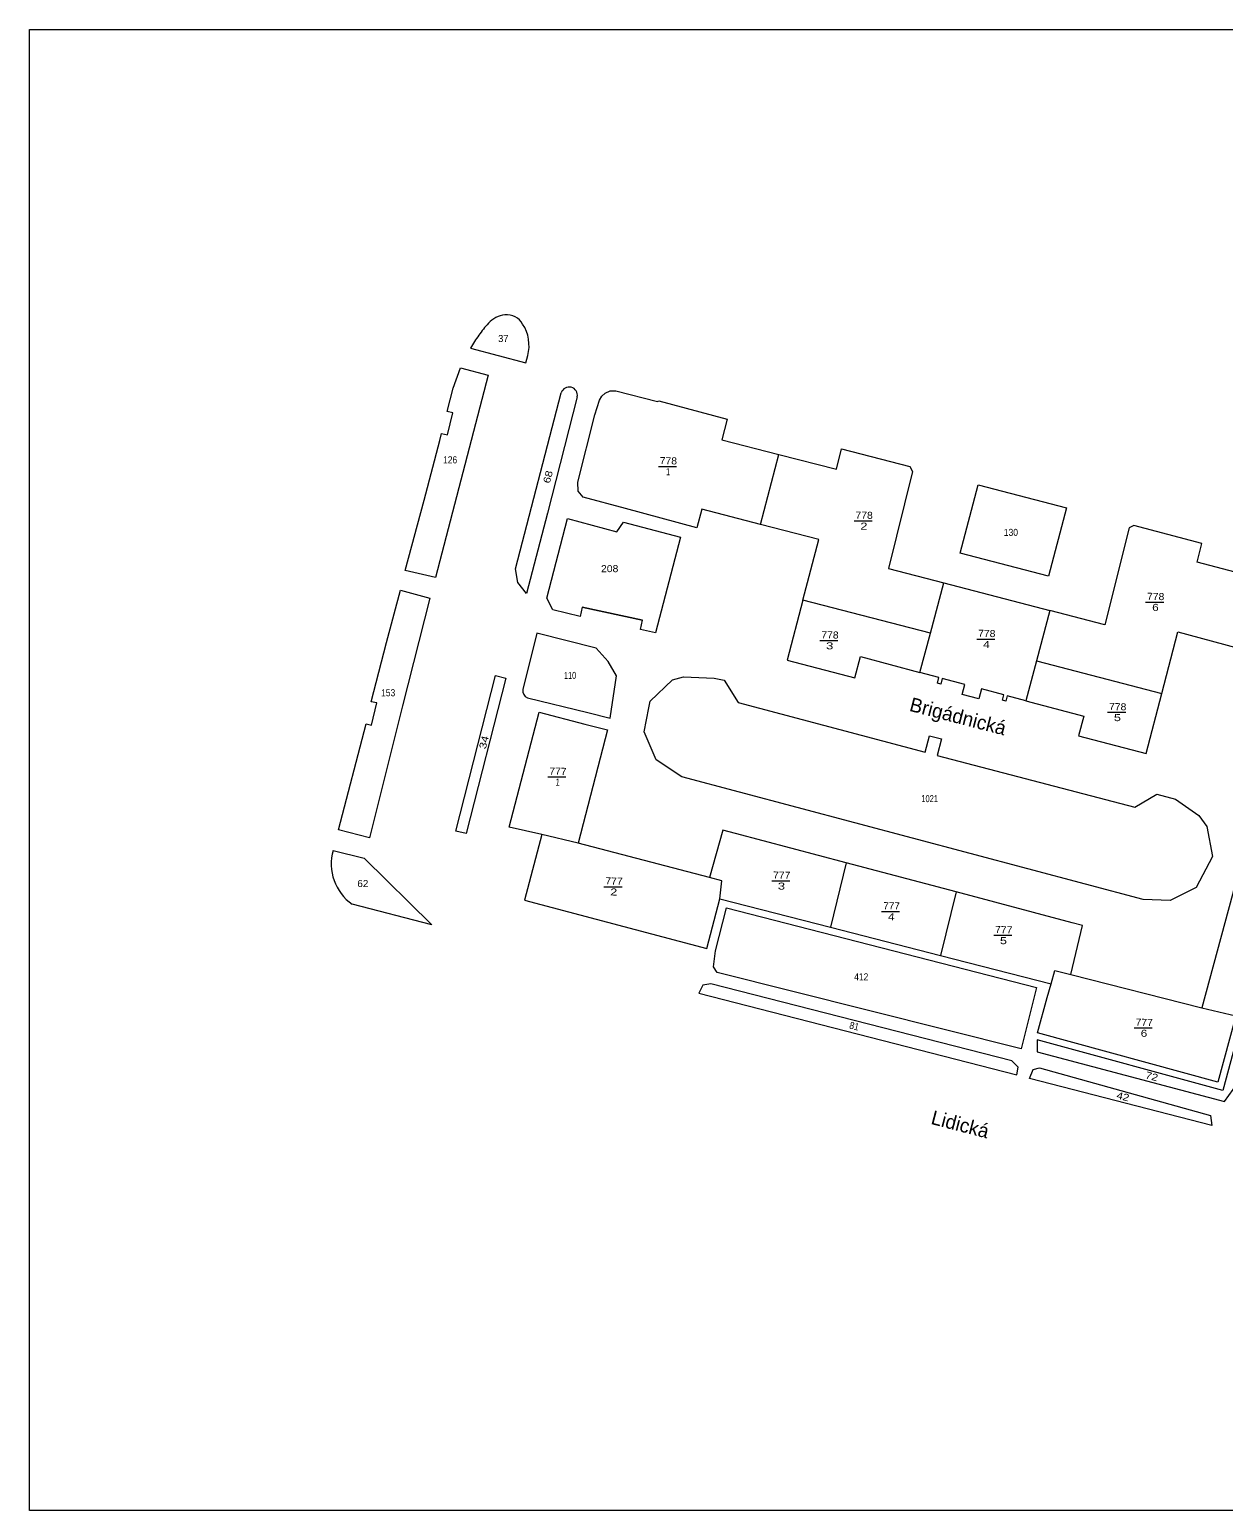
# Model space of a CAD drawing. Extents: x -843443 to -843145, y -1003566 to -1003356.
# Drawn here: x -843442.9 to -843273.6, y -1003566.1 to -1003356.1 of the extents above; entities that cross this region are included whole.
import ezdxf
from ezdxf.enums import TextEntityAlignment as Align

# ---------------------------------------------------------------- set-up
doc = ezdxf.new("R2010")
doc.units = 0
doc.header["$LTSCALE"] = 0.4
doc.layers.add('20', color=7, linetype='Continuous')
for name, color, linetype, lineweight in [('35', 7, 'Continuous', 13), ('38', 7, 'Continuous', 13), ('43', 7, 'Continuous', 13), ('44', 7, 'Continuous', 13)]:
    doc.layers.add(name, color=color, linetype=linetype, lineweight=lineweight)

msp = doc.modelspace()

# ---------------------------------------------------------------- linework, layer by layer
at = {"layer": '35'}
for p, q in [((-843353.765, -1003418.066), (-843351.205, -1003418.066)), ((-843326.004, -1003425.786), (-843323.444, -1003425.786)), ((-843284.663, -1003437.309), (-843282.103, -1003437.309)), ((-843330.851, -1003442.758), (-843328.291, -1003442.758)), ((-843308.615, -1003442.552), (-843306.055, -1003442.552)), ((-843290.05, -1003452.939), (-843287.49, -1003452.939)), ((-843369.424, -1003462.093), (-843366.864, -1003462.093)), ((-843361.475, -1003477.669), (-843358.915, -1003477.669)), ((-843337.695, -1003476.835), (-843335.135, -1003476.835)), ((-843322.113, -1003481.18), (-843319.553, -1003481.18)), ((-843306.214, -1003484.57), (-843303.654, -1003484.57)), ((-843286.286, -1003497.709), (-843283.726, -1003497.709))]:
    msp.add_line(p, q, dxfattribs=at)
at = {"layer": '38'}
for p, q in [((-843327.15, -1003474.27), (-843329.37, -1003483.4)), ((-843311.54, -1003478.41), (-843313.76, -1003487.41))]:
    msp.add_line(p, q, dxfattribs=at)
for points in [[(-843339.26, -1003426.3), (-843347.62, -1003424.13), (-843348.31, -1003426.79), (-843358.44, -1003424.06), (-843364.43, -1003422.42), (-843365.14, -1003421.56), (-843365.19, -1003420.28), (-843362.75, -1003410.74), (-843362.1, -1003408.66), (-843361.79, -1003408.11), (-843361.31, -1003407.67), (-843360.6, -1003407.36), (-843359.81, -1003407.34), (-843353.87, -1003408.86), (-843353.72, -1003408.78), (-843344.03, -1003411.39), (-843344.76, -1003414.3), (-843336.68, -1003416.38)], [(-843333.26, -1003437.02), (-843331.03, -1003428.44), (-843339.26, -1003426.3), (-843336.68, -1003416.38), (-843328.52, -1003418.48), (-843327.79, -1003415.57), (-843318.1, -1003418.09), (-843317.72, -1003418.79), (-843321.15, -1003432.55), (-843313.28, -1003434.6)], [(-843269.27, -1003433.78), (-843277.38, -1003431.66), (-843276.69, -1003428.99), (-843286.35, -1003426.45), (-843287.02, -1003426.78), (-843290.46, -1003440.54), (-843298.24, -1003438.52), (-843300.14, -1003445.64), (-843282.35, -1003450.26), (-843280.09, -1003441.55), (-843271.86, -1003443.76)], [(-843301.65, -1003451.31), (-843304.3, -1003450.6), (-843304.5, -1003451.35), (-843304.97, -1003451.23), (-843304.77, -1003450.48), (-843307.96, -1003449.62), (-843308.33, -1003451.03), (-843310.68, -1003450.41), (-843310.3, -1003449), (-843313.51, -1003448.14), (-843313.73, -1003448.95), (-843314.19, -1003448.83), (-843313.97, -1003448.02), (-843316.68, -1003447.29), (-843315.19, -1003441.72), (-843313.28, -1003434.6), (-843298.24, -1003438.52)], [(-843315.19, -1003441.72), (-843333.26, -1003437.02), (-843335.49, -1003445.57), (-843325.88, -1003448.07), (-843325.08, -1003445.05), (-843316.68, -1003447.29)], [(-843300.14, -1003445.64), (-843301.65, -1003451.31), (-843293.44, -1003453.51), (-843294.19, -1003456.3), (-843284.57, -1003458.8), (-843282.35, -1003450.26)], [(-843370.29, -1003470.29), (-843372.73, -1003479.58), (-843346.91, -1003486.42), (-843345.06, -1003479.38), (-843344.76, -1003476.84), (-843346.53, -1003476.38), (-843365.15, -1003471.48)], [(-843295.27, -1003490.11), (-843293.64, -1003483.16), (-843295.06, -1003482.78), (-843311.54, -1003478.41), (-843327.15, -1003474.27), (-843342.84, -1003470.11), (-843344.6, -1003469.64), (-843346.53, -1003476.38)], [(-843267.1, -1003497.15), (-843262.83, -1003481.4), (-843262.362, -1003479.672), (-843271.96, -1003477.07), (-843272.36, -1003478.76), (-843276.71, -1003494.83)], [(-843345.06, -1003479.38), (-843329.37, -1003483.4), (-843313.76, -1003487.41), (-843298.07, -1003491.44)]]:
    msp.add_lwpolyline(points, dxfattribs=at)
for points in [[(-843370.69, -1003452.93), (-843364.18, -1003454.6), (-843361, -1003455.42), (-843365.15, -1003471.48), (-843370.29, -1003470.29), (-843374.92, -1003469.22)], [(-843300, -1003498.41), (-843298.61, -1003493.41), (-843298.07, -1003491.44), (-843297.556, -1003489.565), (-843295.27, -1003490.11), (-843276.71, -1003494.83), (-843271.88, -1003496), (-843274.44, -1003505.383)]]:
    msp.add_lwpolyline(points, close=True, dxfattribs=at)
at = {"layer": '43'}
for p, q in [((-843364.569, -1003438.014), (-843356.009, -1003439.864)), ((-843354.174, -1003441.669), (-843356.3, -1003441.21)), ((-843385.893, -1003483.063), (-843397.172, -1003480.167))]:
    msp.add_line(p, q, dxfattribs=at)
for points in [[(-843380.42, -1003401.29), (-843372.572, -1003403.361), (-843372.284, -1003402.359)], [(-843372.483, -1003436.085), (-843373.686, -1003434.546), (-843374.004, -1003432.574), (-843367.537, -1003407.623)], [(-843365.264, -1003408.202), (-843369.47, -1003424.72), (-843372.483, -1003436.085)], [(-843372.339, -1003450.901), (-843363.76, -1003452.98), (-843360.58, -1003453.79), (-843359.72, -1003447.77), (-843360.88, -1003445.72), (-843362.57, -1003443.84), (-843371.01, -1003441.72), (-843372.969, -1003449.709)], [(-843399.886, -1003472.516), (-843395.497, -1003473.643), (-843385.893, -1003483.063)]]:
    msp.add_lwpolyline(points, dxfattribs=at)
for points in [[(-843383.704, -1003410.282), (-843382.85, -1003406.95), (-843381.84, -1003404.086), (-843377.88, -1003405.132), (-843385.354, -1003433.806), (-843389.68, -1003432.85), (-843386.96, -1003422.84), (-843384.76, -1003414.4), (-843384.504, -1003413.403), (-843383.644, -1003413.601), (-843382.924, -1003410.461)], [(-843308.42, -1003420.674), (-843295.91, -1003423.94), (-843298.44, -1003433.632), (-843310.95, -1003430.366)], [(-843354.174, -1003441.669), (-843356.3, -1003441.21), (-843356.009, -1003439.864), (-843364.569, -1003438.014), (-843364.86, -1003439.36), (-843368.74, -1003438.42), (-843369.58, -1003436.74), (-843366.66, -1003425.44), (-843359.65, -1003427.35), (-843358.72, -1003425.99), (-843350.632, -1003428.101)], [(-843399.14, -1003469.61), (-843395.21, -1003454.58), (-843394.43, -1003454.759), (-843393.71, -1003451.619), (-843394.49, -1003451.44), (-843392.32, -1003443.05), (-843390.351, -1003435.626), (-843386.165, -1003436.737), (-843390.04, -1003452.04), (-843394.747, -1003470.72)], [(-843382.495, -1003469.779), (-843376.852, -1003447.715), (-843375.398, -1003448.086), (-843381.042, -1003470.15)], [(-843277.1, -1003467.59), (-843275.98, -1003469.15), (-843275.18, -1003473.4), (-843277.51, -1003477.8), (-843281.2, -1003479.62), (-843285.03, -1003479.49), (-843350.44, -1003462.1), (-843354.08, -1003459.68), (-843355.78, -1003455.73), (-843355.113, -1003452.327), (-843354.92, -1003451.34), (-843351.737, -1003448.324), (-843350.19, -1003447.89), (-843345.85, -1003448.11), (-843344.436, -1003448.369), (-843342.47, -1003451.55), (-843315.93, -1003458.58), (-843315.32, -1003456.26), (-843313.63, -1003456.7), (-843314.25, -1003459.05), (-843286.2, -1003466.4), (-843283.064, -1003464.57), (-843280.43, -1003465.26)], [(-843300.125, -1003491.953), (-843302.306, -1003500.644), (-843345.41, -1003489.83), (-843345.93, -1003489.05), (-843345.65, -1003486.75), (-843344.09, -1003480.661)], [(-843302.95, -1003504.36), (-843302.72, -1003503.26), (-843303.64, -1003502.35), (-843346.33, -1003491.43), (-843347.44, -1003491.62), (-843348.01, -1003492.79)], [(-843273.731, -1003506.584), (-843300.026, -1003499.41), (-843300.07, -1003501.07), (-843273.496, -1003508.115), (-843270.42, -1003503.86), (-843268.08, -1003499.33), (-843267.1, -1003497.15), (-843270.908, -1003496.234)], [(-843301.14, -1003504.87), (-843300.63, -1003503.58), (-843299.7, -1003503.34), (-843275.48, -1003510.11), (-843275.29, -1003511.54)]]:
    msp.add_lwpolyline(points, close=True, dxfattribs=at)
for centre, radius, start, end in [((-843375.0875, -1003400.3262), 3.7711, 96.58603, 137.32493), ((-843375.2299, -1003399.0929), 2.5296, 28.65214, 96.58602), ((-843366.3841, -1003408.3504), 15.609, 137.32493, 145.32825), ((-843377.7161, -1003400.9414), 5.6143, 345.37788, 33.04485), ((-843360.1392, -1003413.3488), 23.595, 143.97263, 149.2647), ((-843366.4202, -1003407.9896), 1.1752, 349.58933, 161.84149), ((-843371.8822, -1003449.8968), 1.1033, 170.17263, 245.53093), ((-843393.1695, -1003474.4401), 6.9869, 164.01292, 235.04705)]:
    msp.add_arc(centre, radius, start, end, dxfattribs=at)
at = {"layer": '44'}
msp.add_lwpolyline([(-843442.925, -1003356.123), (-843144.925, -1003356.123), (-843144.925, -1003566.123), (-843442.925, -1003566.123)], close=True, dxfattribs=at)

# ---------------------------------------------------------------- texts
at = {"layer": '20'}
for s, height, rotation, p in [('Brigádnická', 2, 345.435, (-843318.282, -1003452.716)), ('Lidická', 1.999, 345.434, (-843315.229, -1003511.297))]:
    msp.add_text(s, height=height, rotation=rotation, dxfattribs=at).set_placement(p)
at = {"layer": '35'}
for s, width, p in [('778', 1.1, (-843352.3545, -1003417.7685)), ('1', 0.7, (-843352.3885, -1003419.3178)), ('778', 1.1, (-843324.5935, -1003425.4885)), ('2', 1.35, (-843324.627, -1003427.0383)), ('778', 1.1, (-843283.2525, -1003437.0115)), ('6', 1.25, (-843283.2855, -1003438.5614)), ('778', 1.1, (-843329.439, -1003442.4605)), ('3', 1.4, (-843329.4745, -1003444.0105)), ('778', 1.1, (-843307.203, -1003442.2555)), ('4', 1.25, (-843307.2375, -1003443.8044)), ('778', 1.1, (-843288.639, -1003452.6425)), ('5', 1.35, (-843288.673, -1003454.192)), ('777', 1.1, (-843368.0125, -1003461.7957)), ('1', 0.7, (-843368.0485, -1003463.3458)), ('777', 1.1, (-843360.0625, -1003477.3727)), ('777', 1.1, (-843336.2825, -1003476.5377)), ('2', 1.35, (-843360.098, -1003478.9223)), ('3', 1.4, (-843336.3185, -1003478.0875)), ('777', 1.05, (-843320.702, -1003480.8827)), ('4', 1.25, (-843320.7355, -1003482.4324)), ('777', 1.1, (-843304.8015, -1003484.2727)), ('5', 1.35, (-843304.837, -1003485.823)), ('777', 1.1, (-843284.8745, -1003497.4127)), ('6', 1.25, (-843284.9095, -1003498.9614))]:
    msp.add_text(s, height=1, rotation=358.734, dxfattribs=dict(at, width=width)).set_placement(p, align=Align.CENTER)
at = {"layer": '43'}
msp.add_text('37', height=1, dxfattribs=at).set_placement((-843376.493, -1003400.429))
for s, width, p in [('126', 0.9, (-843384.298, -1003417.632)), ('130', 0.9, (-843304.776, -1003427.922)), ('208', 1.1, (-843361.894, -1003433.067)), ('110', 0.65, (-843367.149, -1003448.204)), ('153', 0.9, (-843393.084, -1003450.667)), ('1021', 0.8, (-843316.48, -1003465.684)), ('62', 1.05, (-843396.45, -1003477.724)), ('412', 0.9, (-843325.994, -1003490.948))]:
    msp.add_text(s, height=1, dxfattribs=dict(at, width=width)).set_placement(p)
for s, height, rotation, width, p in [('68', 1, 75.47, 1.2, (-843369.162, -1003420.546)), ('34', 1, 75.653, 1.25, (-843378.249, -1003458.219)), ('81', 1, 345.652, 0.9, (-843326.754, -1003497.762)), ('72', 0.999, 344.74, 1.2, (-843284.786, -1003504.818)), ('42', 1, 345.532, 1.2, (-843288.865, -1003507.692))]:
    msp.add_text(s, height=height, rotation=rotation, dxfattribs=dict(at, width=width)).set_placement(p)

doc.saveas('drawing.dxf')
